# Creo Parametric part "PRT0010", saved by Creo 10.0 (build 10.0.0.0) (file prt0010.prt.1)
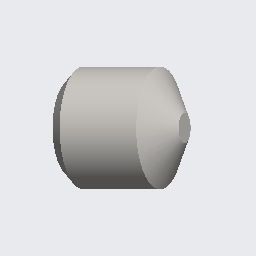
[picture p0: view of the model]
Units: millimeter Newton Second (mmNs); MM, TONNE, SECS

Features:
  1. coordinate system "61910404"
  2. imported feature "Import-ke ID 4"

Other named items: NOTE_0

Notes: 61910404

Surfaces: 9 plane, 4 cone, 2 cylinder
